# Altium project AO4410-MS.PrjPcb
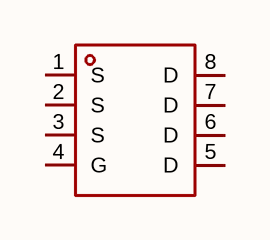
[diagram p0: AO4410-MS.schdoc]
1 sheet, 1 parts. Net scope: global (net labels, ports and power ports of the same name join across sheets).

## Sheet AO4410-MS.schdoc
size 127 x 101 mm

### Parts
Q?  ao4410-ms  [SOP-8_L5.0-W4.0-P1.27-LS6.2-BL]  (value not drawn)

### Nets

Not connected (* = marked no-connect by the designer): Q? 1(S) 2(S) 3(S) 4(G) 5(D) 6(D) 7(D) 8(D)

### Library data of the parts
Q? = ao4410-ms: 数量:1个N沟道;漏源电压(Vdss):30V;连续漏极电流(Id):15A;导通电阻(RDS(on)):7.5mΩ@10V;耗散功率(Pd):1.5W;阈值电压(Vgs(th)):1.5V;; Manufacturer: MSKSEMI(美森科); AddInBom: yes; ModelId: a3315c1c78f949e6bb82c6eaca1c53c7; ModelName: SOP-8_L5.0-W4.0-H1.8-LS6.2-P1.27; ModelTransform: 244.094,196.85,0,90,0,0,0,0,0; Number: 1个N沟道; Drain to Source Voltage: 30V; Current - Continuous Drain(Id): 15A; Pd - Power Dissipation: 1.5W; Gate Threshold Voltage (Vgs(th)): 1.5V; Gate Charge(Qg): 12.6nC@4.5V; Input Capacitance(Ciss): 1.317nF; Reverse Transfer Capacitance (Crss@Vds): 131pF; Type: N沟道; Output Capacitance(Coss): 163pF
